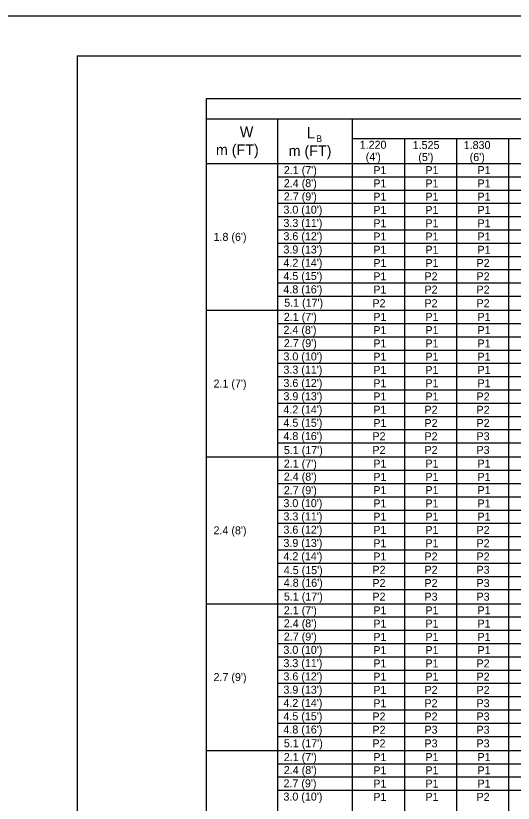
# Model space of a CAD drawing. Extents: x 637580 to 641008, y 294594 to 295782.
# Drawn here: x 638438.3 to 638624.8, y 295486.5 to 295781.6 of the extents above; entities that cross this region are included whole.
import ezdxf

# ---------------------------------------------------------------- set-up
doc = ezdxf.new("R2010")
doc.units = 0
for name, color, linetype in [('1', 7, 'Continuous'), ('2', 7, 'Continuous'), ('PLT-BNDY', 7, 'Continuous')]:
    doc.layers.add(name, color=color, linetype=linetype)

msp = doc.modelspace()

# ---------------------------------------------------------------- linework, layer by layer
at = {"layer": '1'}
for p, q in [((638461.31, 295766.63), (639247.31, 295766.63)), ((638461.31, 295766.63), (638461.31, 295202.63)), ((638509.81, 295750.63), (638876.73, 295750.63)), ((638509.81, 295231.34), (638509.81, 295750.63)), ((638509.81, 295742.95), (638876.73, 295742.95)), ((638536.61, 295231.34), (638536.61, 295742.95)), ((638564.61, 295231.34), (638564.61, 295742.95)), ((638584.12, 295231.34), (638584.12, 295735.61)), ((638603.63, 295231.34), (638603.63, 295735.61)), ((638623.14, 295231.34), (638623.14, 295735.61)), ((638509.81, 295726.25), (638876.73, 295726.25)), ((638509.81, 295671.26), (638876.73, 295671.26)), ((638509.81, 295616.27), (638876.73, 295616.27)), ((638509.81, 295561.28), (638876.73, 295561.28)), ((638509.81, 295506.29), (638876.73, 295506.29))]:
    msp.add_line(p, q, dxfattribs=at)
at = {"layer": '2'}
for p, q in [((638564.61, 295735.61), (638876.73, 295735.61)), ((638536.61, 295721.27), (638876.73, 295721.27)), ((638536.61, 295716.3), (638876.73, 295716.3)), ((638536.61, 295711.33), (638876.73, 295711.33)), ((638536.61, 295706.36), (638876.73, 295706.36)), ((638536.61, 295701.39), (638876.73, 295701.39)), ((638536.61, 295696.41), (638876.73, 295696.41)), ((638536.61, 295691.44), (638876.73, 295691.44)), ((638536.61, 295686.47), (638876.73, 295686.47)), ((638536.61, 295681.5), (638876.73, 295681.5)), ((638536.61, 295676.52), (638876.73, 295676.52)), ((638536.61, 295666.29), (638876.73, 295666.29)), ((638536.61, 295661.31), (638876.73, 295661.31)), ((638536.61, 295656.34), (638876.73, 295656.34)), ((638536.61, 295651.37), (638876.73, 295651.37)), ((638536.61, 295646.4), (638876.73, 295646.4)), ((638536.61, 295641.42), (638876.73, 295641.42)), ((638536.61, 295636.45), (638876.73, 295636.45)), ((638536.61, 295631.48), (638876.73, 295631.48)), ((638536.61, 295626.51), (638876.73, 295626.51)), ((638536.61, 295621.53), (638876.73, 295621.53)), ((638536.61, 295611.3), (638876.73, 295611.3)), ((638536.61, 295606.32), (638876.73, 295606.32)), ((638536.61, 295601.35), (638876.73, 295601.35)), ((638536.61, 295596.38), (638876.73, 295596.38)), ((638536.61, 295591.41), (638876.73, 295591.41)), ((638536.61, 295586.43), (638876.73, 295586.43)), ((638536.61, 295581.46), (638876.73, 295581.46)), ((638536.61, 295576.49), (638876.73, 295576.49)), ((638536.61, 295571.52), (638876.73, 295571.52)), ((638536.61, 295566.54), (638876.73, 295566.54)), ((638536.61, 295556.31), (638876.73, 295556.31)), ((638536.61, 295551.33), (638876.73, 295551.33)), ((638536.61, 295546.36), (638876.73, 295546.36)), ((638536.61, 295541.39), (638876.73, 295541.39)), ((638536.61, 295536.42), (638876.73, 295536.42)), ((638536.61, 295531.44), (638876.73, 295531.44)), ((638536.61, 295526.47), (638876.73, 295526.47)), ((638536.61, 295521.5), (638876.73, 295521.5)), ((638536.61, 295516.53), (638876.73, 295516.53)), ((638536.61, 295511.55), (638876.73, 295511.55)), ((638536.61, 295501.32), (638876.73, 295501.32)), ((638536.61, 295496.34), (638876.73, 295496.34)), ((638536.61, 295491.37), (638876.73, 295491.37))]:
    msp.add_line(p, q, dxfattribs=at)
at = {"layer": 'PLT-BNDY'}
msp.add_lwpolyline([(638421.31, 295781.63), (639262.31, 295781.63), (639262.31, 295187.63), (638421.31, 295187.63)], close=True, dxfattribs=at)

# ---------------------------------------------------------------- texts
at = {"layer": '1'}
for s, height, p in [('W', 4, (638522.33, 295736.12)), ('L', 4.3, (638547.36, 295735.64)), ('B', 2.5, (638550.91, 295734.33)), ('m (FT)', 4.003, (638513.35, 295729.41)), ('m (FT)', 4.003, (638540.61, 295729.01)), ('1.220', 3, (638567.25, 295731.77)), ('1.525', 3, (638587.11, 295731.67)), ('1.830', 3, (638606.23, 295731.67)), ("(4')", 3, (638569.5, 295727.27)), ("(5')", 3, (638589.22, 295727.17)), ("(6')", 3, (638608.48, 295727.17)), ("2.1 (7')", 3, (638538.82, 295722.26)), ('P1', 3, (638572.36, 295722.26)), ('P1', 3, (638591.87, 295722.26)), ('P1', 3, (638611.38, 295722.26)), ("2.4 (8')", 3, (638538.82, 295717.38)), ('P1', 3, (638572.36, 295717.29)), ('P1', 3, (638591.87, 295717.29)), ('P1', 3, (638611.38, 295717.29)), ("2.7 (9')", 3, (638538.82, 295712.41)), ('P1', 3, (638572.36, 295712.32)), ('P1', 3, (638591.87, 295712.32)), ('P1', 3, (638611.38, 295712.32)), ("3.0 (10')", 3, (638538.67, 295707.44)), ('P1', 3, (638572.36, 295707.34)), ('P1', 3, (638591.87, 295707.34)), ('P1', 3, (638611.38, 295707.34)), ("3.3 (11')", 3, (638538.67, 295702.47)), ('P1', 3, (638572.36, 295702.37)), ('P1', 3, (638591.87, 295702.37)), ('P1', 3, (638611.38, 295702.37)), ("1.8 (6')", 3, (638512.47, 295697.25)), ("3.6 (12')", 3, (638538.67, 295697.49)), ('P1', 3, (638572.36, 295697.4)), ('P1', 3, (638591.87, 295697.4)), ('P1', 3, (638611.38, 295697.4)), ("3.9 (13')", 3, (638538.67, 295692.52)), ('P1', 3, (638572.36, 295692.43)), ('P1', 3, (638591.87, 295692.43)), ('P1', 3, (638611.38, 295692.43)), ("4.2 (14')", 3, (638538.67, 295687.55)), ('P1', 3, (638572.36, 295687.45)), ('P1', 3, (638591.87, 295687.45)), ('P2', 3, (638611.03, 295687.45)), ("4.5 (15')", 3, (638538.67, 295682.58)), ('P1', 3, (638572.36, 295682.48)), ('P2', 3, (638591.53, 295682.48)), ('P2', 3, (638611.03, 295682.48)), ("4.8 (16')", 3, (638538.67, 295677.6)), ('P1', 3, (638572.36, 295677.51)), ('P2', 3, (638591.53, 295677.51)), ('P2', 3, (638611.03, 295677.51)), ("5.1 (17')", 3, (638538.95, 295672.58)), ('P2', 3, (638572.02, 295672.39)), ('P2', 3, (638591.53, 295672.39)), ('P2', 3, (638611.03, 295672.39)), ("2.1 (7')", 3, (638538.82, 295667.27)), ('P1', 3, (638572.36, 295667.27)), ('P1', 3, (638591.87, 295667.27)), ('P1', 3, (638611.38, 295667.27)), ("2.4 (8')", 3, (638538.7, 295662.39)), ('P1', 3, (638572.36, 295662.3)), ('P1', 3, (638591.87, 295662.3)), ('P1', 3, (638611.38, 295662.3)), ("2.7 (9')", 3, (638538.82, 295657.42)), ('P1', 3, (638572.36, 295657.33)), ('P1', 3, (638591.87, 295657.33)), ('P1', 3, (638611.38, 295657.33)), ("3.0 (10')", 3, (638538.67, 295652.45)), ('P1', 3, (638572.36, 295652.35)), ('P1', 3, (638591.87, 295652.35)), ('P1', 3, (638611.38, 295652.35)), ("3.3 (11')", 3, (638538.67, 295647.48)), ('P1', 3, (638572.36, 295647.38)), ('P1', 3, (638591.87, 295647.38)), ('P1', 3, (638611.38, 295647.38)), ("2.1 (7')", 3, (638512.47, 295642.26)), ("3.6 (12')", 3, (638538.67, 295642.5)), ('P1', 3, (638572.36, 295642.41)), ('P1', 3, (638591.87, 295642.41)), ('P1', 3, (638611.38, 295642.41)), ("3.9 (13')", 3, (638538.67, 295637.53)), ('P1', 3, (638572.36, 295637.44)), ('P1', 3, (638591.87, 295637.44)), ('P2', 3, (638611.03, 295637.44)), ("4.2 (14')", 3, (638538.67, 295632.56)), ('P1', 3, (638572.36, 295632.46)), ('P2', 3, (638591.53, 295632.46)), ('P2', 3, (638611.03, 295632.46)), ("4.5 (15')", 3, (638538.67, 295627.59)), ('P1', 3, (638572.36, 295627.49)), ('P2', 3, (638591.53, 295627.49)), ('P2', 3, (638611.03, 295627.49)), ("4.8 (16')", 3, (638538.67, 295622.61)), ('P2', 3, (638572.02, 295622.52)), ('P2', 3, (638591.53, 295622.52)), ('P3', 3, (638611.03, 295622.52)), ("5.1 (17')", 3, (638538.83, 295617.34)), ('P2', 3, (638572.02, 295617.4)), ('P2', 3, (638591.53, 295617.4)), ('P3', 3, (638611.03, 295617.4)), ("2.1 (7')", 3, (638538.82, 295612.28)), ('P1', 3, (638572.36, 295612.28)), ('P1', 3, (638591.87, 295612.28)), ('P1', 3, (638611.38, 295612.28)), ("2.4 (8')", 3, (638538.82, 295607.4)), ('P1', 3, (638572.36, 295607.31)), ('P1', 3, (638591.87, 295607.31)), ('P1', 3, (638611.38, 295607.31)), ("2.7 (9')", 3, (638538.82, 295602.31)), ('P1', 3, (638572.36, 295602.34)), ('P1', 3, (638591.87, 295602.34)), ('P1', 3, (638611.38, 295602.34)), ("3.0 (10')", 3, (638538.67, 295597.46)), ('P1', 3, (638572.36, 295597.36)), ('P1', 3, (638591.87, 295597.36)), ('P1', 3, (638611.38, 295597.36)), ("3.3 (11')", 3, (638538.67, 295592.49)), ('P1', 3, (638572.36, 295592.39)), ('P1', 3, (638591.87, 295592.39)), ('P1', 3, (638611.38, 295592.39)), ("2.4 (8')", 3, (638512.47, 295587.27)), ("3.6 (12')", 3, (638538.67, 295587.51)), ('P1', 3, (638572.36, 295587.42)), ('P1', 3, (638591.87, 295587.42)), ('P2', 3, (638611.03, 295587.42)), ("3.9 (13')", 3, (638538.67, 295582.54)), ('P1', 3, (638572.36, 295582.45)), ('P1', 3, (638591.87, 295582.45)), ('P2', 3, (638611.03, 295582.45)), ("4.2 (14')", 3, (638538.67, 295577.57)), ('P1', 3, (638572.36, 295577.47)), ('P2', 3, (638591.53, 295577.47)), ('P2', 3, (638611.03, 295577.47)), ("4.5 (15')", 3, (638538.8, 295572.35)), ('P2', 3, (638572.02, 295572.5)), ('P2', 3, (638591.53, 295572.5)), ('P3', 3, (638611.03, 295572.5)), ("4.8 (16')", 3, (638538.8, 295567.62)), ('P2', 3, (638572.02, 295567.53)), ('P2', 3, (638591.53, 295567.53)), ('P3', 3, (638611.03, 295567.53)), ("5.1 (17')", 3, (638538.83, 295562.47)), ('P2', 3, (638572.02, 295562.41)), ('P3', 3, (638591.53, 295562.41)), ('P3', 3, (638611.03, 295562.41)), ("2.1 (7')", 3, (638538.82, 295557.29)), ('P1', 3, (638572.36, 295557.29)), ('P1', 3, (638591.87, 295557.29)), ('P1', 3, (638611.38, 295557.29)), ("2.4 (8')", 3, (638538.82, 295552.41)), ('P1', 3, (638572.36, 295552.32)), ('P1', 3, (638591.87, 295552.32)), ('P1', 3, (638611.38, 295552.32)), ("2.7 (9')", 3, (638538.82, 295547.44)), ('P1', 3, (638572.36, 295547.35)), ('P1', 3, (638591.87, 295547.35)), ('P1', 3, (638611.38, 295547.35)), ("3.0 (10')", 3, (638538.67, 295542.47)), ('P1', 3, (638572.36, 295542.37)), ('P1', 3, (638591.87, 295542.37)), ('P1', 3, (638611.38, 295542.37)), ("3.3 (11')", 3, (638538.67, 295537.5)), ('P1', 3, (638572.36, 295537.4)), ('P1', 3, (638591.87, 295537.4)), ('P2', 3, (638611.03, 295537.4)), ("2.7 (9')", 3, (638512.47, 295532.28)), ("3.6 (12')", 3, (638538.67, 295532.52)), ('P1', 3, (638572.36, 295532.43)), ('P1', 3, (638591.87, 295532.43)), ('P2', 3, (638611.03, 295532.43)), ("3.9 (13')", 3, (638538.67, 295527.55)), ('P1', 3, (638572.36, 295527.46)), ('P2', 3, (638591.53, 295527.46)), ('P2', 3, (638611.03, 295527.46)), ("4.2 (14')", 3, (638538.67, 295522.58)), ('P1', 3, (638572.36, 295522.48)), ('P2', 3, (638591.53, 295522.48)), ('P3', 3, (638611.03, 295522.48)), ("4.5 (15')", 3, (638538.67, 295517.61)), ('P2', 3, (638572.02, 295517.51)), ('P2', 3, (638591.53, 295517.51)), ('P3', 3, (638611.03, 295517.51)), ("4.8 (16')", 3, (638538.67, 295512.63)), ('P2', 3, (638572.02, 295512.54)), ('P3', 3, (638591.53, 295512.54)), ('P3', 3, (638611.03, 295512.54)), ("5.1 (17')", 3, (638538.83, 295507.48)), ('P2', 3, (638572.02, 295507.42)), ('P3', 3, (638591.53, 295507.42)), ('P3', 3, (638611.03, 295507.42)), ("2.1 (7')", 3, (638538.82, 295502.3)), ('P1', 3, (638572.36, 295502.3)), ('P1', 3, (638591.87, 295502.3)), ('P1', 3, (638611.38, 295502.3)), ("2.4 (8')", 3, (638538.82, 295497.42)), ('P1', 3, (638572.36, 295497.33)), ('P1', 3, (638591.87, 295497.33)), ('P1', 3, (638611.38, 295497.33)), ("2.7 (9')", 3, (638538.7, 295492.45)), ('P1', 3, (638572.36, 295492.36)), ('P1', 3, (638591.87, 295492.36)), ('P1', 3, (638611.38, 295492.36)), ("3.0 (10')", 3, (638538.67, 295487.48)), ('P1', 3, (638572.36, 295487.38)), ('P1', 3, (638591.87, 295487.38)), ('P2', 3, (638611.03, 295487.38))]:
    msp.add_text(s, height=height, dxfattribs=at).set_placement(p)

doc.saveas('drawing.dxf')
